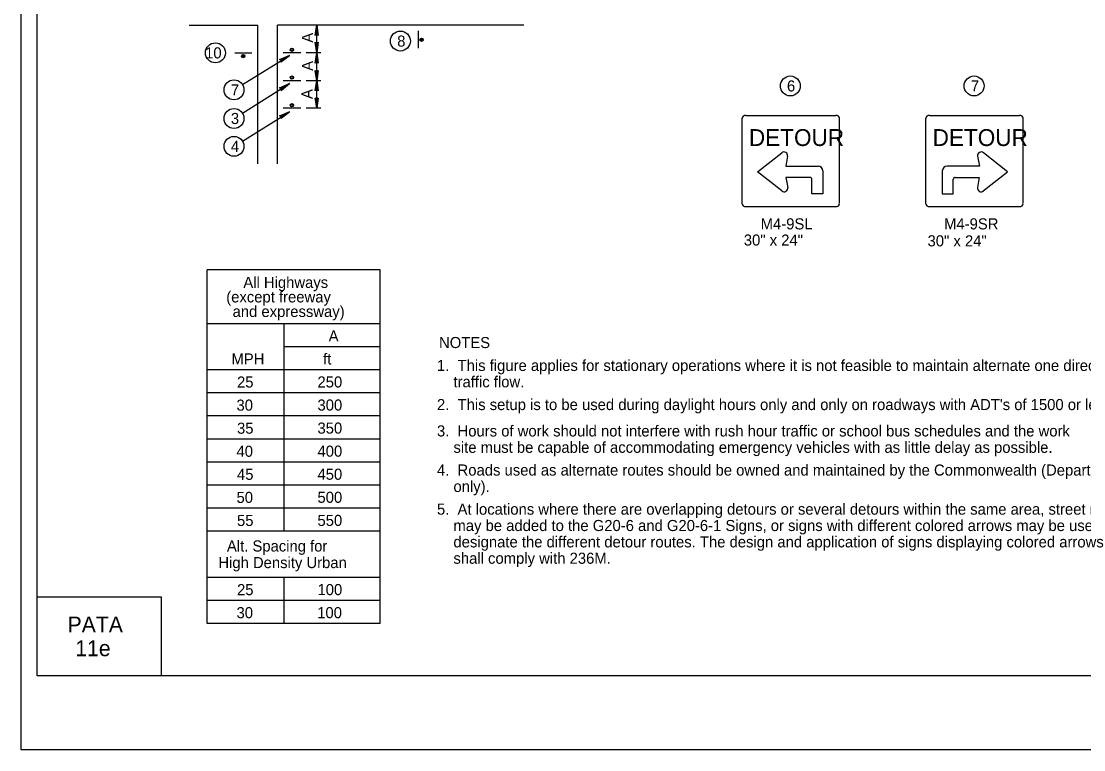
# Model space of a CAD drawing. Extents: x -14145 to -13662, y 30244 to 30661.
# Drawn here: x -13790.17 to -13770.05, y 30451.81 to 30465.61 of the extents above; entities that cross this region are included whole.
import ezdxf

# ---------------------------------------------------------------- set-up
doc = ezdxf.new("R2010")
doc.units = 0
for name, color, linetype in [('1', 7, 'Continuous'), ('10', 7, 'Continuous'), ('2', 7, 'Continuous'), ('3', 7, 'Continuous'), ('4', 7, 'Continuous'), ('61', 7, 'Continuous')]:
    doc.layers.add(name, color=color, linetype=linetype)

msp = doc.modelspace()

# ---------------------------------------------------------------- linework, layer by layer
at = {"layer": '1'}
for p, q in [((-13786.996, 30465.537), (-13785.691, 30465.537)), ((-13785.691, 30462.907), (-13785.691, 30465.537)), ((-13785.319, 30462.907), (-13785.319, 30465.537)), ((-13780.654, 30465.537), (-13785.319, 30465.537)), ((-13784.575, 30465.01), (-13784.575, 30465.544)), ((-13782.649, 30465.098), (-13782.649, 30465.429)), ((-13786.13, 30465.01), (-13785.806, 30465.01)), ((-13785.982, 30464.415), (-13785.096, 30464.963)), ((-13784.88, 30465.01), (-13785.211, 30465.01)), ((-13784.501, 30465.01), (-13784.778, 30465.01)), ((-13784.575, 30464.483), (-13784.575, 30465.01)), ((-13785.982, 30463.867), (-13785.096, 30464.429)), ((-13784.88, 30464.483), (-13785.211, 30464.483)), ((-13784.501, 30464.483), (-13784.778, 30464.483)), ((-13784.575, 30463.962), (-13784.575, 30464.489)), ((-13784.88, 30463.962), (-13785.211, 30463.962)), ((-13784.501, 30463.962), (-13784.778, 30463.962)), ((-13785.982, 30463.34), (-13785.096, 30463.894)), ((-13776.52, 30462.152), (-13776.52, 30463.774)), ((-13776.45, 30463.827), (-13774.748, 30463.827)), ((-13774.677, 30462.157), (-13774.677, 30463.774)), ((-13773.04, 30462.152), (-13773.04, 30463.774)), ((-13772.97, 30463.827), (-13771.268, 30463.827)), ((-13771.197, 30462.157), (-13771.197, 30463.774)), ((-13776.227, 30462.759), (-13775.77, 30463.12)), ((-13771.491, 30462.759), (-13771.948, 30463.12)), ((-13775.658, 30463.057), (-13775.692, 30462.866)), ((-13772.06, 30463.057), (-13772.026, 30462.866)), ((-13775.765, 30462.395), (-13776.227, 30462.759)), ((-13775.692, 30462.866), (-13775.082, 30462.866)), ((-13774.99, 30462.775), (-13774.99, 30462.343)), ((-13772.728, 30462.775), (-13772.728, 30462.343)), ((-13772.026, 30462.866), (-13772.636, 30462.866)), ((-13771.953, 30462.395), (-13771.491, 30462.759)), ((-13775.235, 30462.653), (-13775.689, 30462.653)), ((-13775.689, 30462.653), (-13775.654, 30462.46)), ((-13775.198, 30462.343), (-13775.198, 30462.616)), ((-13772.52, 30462.343), (-13772.52, 30462.616)), ((-13772.483, 30462.653), (-13772.029, 30462.653)), ((-13772.029, 30462.653), (-13772.064, 30462.46)), ((-13774.99, 30462.343), (-13775.198, 30462.343)), ((-13772.728, 30462.343), (-13772.52, 30462.343)), ((-13774.748, 30462.096), (-13776.45, 30462.096)), ((-13771.268, 30462.096), (-13772.97, 30462.096)), ((-13786.651, 30454.198), (-13786.651, 30460.898)), ((-13783.374, 30460.898), (-13786.651, 30460.898)), ((-13783.374, 30454.198), (-13783.374, 30460.898)), ((-13783.374, 30459.879), (-13786.653, 30459.879)), ((-13785.195, 30455.946), (-13785.195, 30459.879)), ((-13783.374, 30459.442), (-13785.195, 30459.442)), ((-13783.374, 30459.005), (-13786.653, 30459.005)), ((-13783.374, 30458.568), (-13786.653, 30458.568)), ((-13783.374, 30458.131), (-13786.653, 30458.131)), ((-13783.374, 30457.694), (-13786.653, 30457.694)), ((-13783.374, 30457.257), (-13786.653, 30457.257)), ((-13783.374, 30456.82), (-13786.653, 30456.82)), ((-13783.374, 30456.383), (-13786.653, 30456.383)), ((-13783.374, 30455.946), (-13786.653, 30455.946)), ((-13783.374, 30455.072), (-13786.653, 30455.072)), ((-13785.195, 30454.198), (-13785.195, 30455.072)), ((-13783.374, 30454.635), (-13786.653, 30454.635)), ((-13783.374, 30454.198), (-13786.651, 30454.198))]:
    msp.add_line(p, q, dxfattribs=at)
for points in [[(-13784.602, 30465.355), (-13784.589, 30465.362), (-13784.575, 30465.544), (-13784.602, 30465.355), (-13784.609, 30465.341), (-13784.575, 30465.544), (-13784.569, 30465.362), (-13784.555, 30465.355), (-13784.575, 30465.544), (-13784.548, 30465.341), (-13784.555, 30465.355)], [(-13784.555, 30465.199), (-13784.569, 30465.192), (-13784.575, 30465.01), (-13784.555, 30465.199), (-13784.548, 30465.213), (-13784.575, 30465.01), (-13784.589, 30465.192), (-13784.602, 30465.199), (-13784.575, 30465.01), (-13784.609, 30465.213), (-13784.602, 30465.199)], [(-13785.272, 30464.888), (-13785.258, 30464.882), (-13785.096, 30464.963), (-13785.272, 30464.888), (-13785.285, 30464.888), (-13785.096, 30464.963), (-13785.245, 30464.861), (-13785.245, 30464.848), (-13785.096, 30464.963), (-13785.251, 30464.834), (-13785.245, 30464.848)], [(-13784.602, 30464.821), (-13784.589, 30464.834), (-13784.575, 30465.01), (-13784.602, 30464.821), (-13784.609, 30464.814), (-13784.575, 30465.01), (-13784.569, 30464.834), (-13784.555, 30464.827), (-13784.575, 30465.01), (-13784.548, 30464.814), (-13784.555, 30464.827)], [(-13784.555, 30464.672), (-13784.569, 30464.665), (-13784.575, 30464.483), (-13784.555, 30464.672), (-13784.548, 30464.679), (-13784.575, 30464.483), (-13784.589, 30464.665), (-13784.602, 30464.672), (-13784.575, 30464.483), (-13784.609, 30464.679), (-13784.602, 30464.672)], [(-13785.272, 30464.341), (-13785.258, 30464.334), (-13785.096, 30464.429), (-13785.272, 30464.341), (-13785.285, 30464.347), (-13785.096, 30464.429), (-13785.245, 30464.32), (-13785.245, 30464.307), (-13785.096, 30464.429), (-13785.251, 30464.293), (-13785.245, 30464.307)], [(-13784.602, 30464.307), (-13784.589, 30464.314), (-13784.575, 30464.489), (-13784.602, 30464.307), (-13784.609, 30464.293), (-13784.575, 30464.489), (-13784.569, 30464.314), (-13784.555, 30464.307), (-13784.575, 30464.489), (-13784.548, 30464.293), (-13784.555, 30464.307)], [(-13784.555, 30464.151), (-13784.569, 30464.145), (-13784.575, 30463.962), (-13784.555, 30464.151), (-13784.548, 30464.151), (-13784.575, 30463.962), (-13784.589, 30464.145), (-13784.602, 30464.151), (-13784.575, 30463.962), (-13784.609, 30464.151), (-13784.602, 30464.151)], [(-13785.272, 30463.82), (-13785.258, 30463.813), (-13785.096, 30463.894), (-13785.272, 30463.82), (-13785.285, 30463.82), (-13785.096, 30463.894), (-13785.245, 30463.793), (-13785.245, 30463.78), (-13785.096, 30463.894), (-13785.251, 30463.766), (-13785.245, 30463.78)]]:
    msp.add_lwpolyline(points, dxfattribs=at)
for centre, radius in [((-13782.993, 30465.236), 0.189), ((-13786.496, 30465.012), 0.189), ((-13782.59, 30465.259), 0.0314), ((-13785.968, 30464.951), 0.0314), ((-13785.048, 30465.072), 0.0314), ((-13785.048, 30464.544), 0.0314), ((-13775.607, 30464.385), 0.189), ((-13772.127, 30464.385), 0.189), ((-13786.144, 30464.311), 0.189), ((-13786.144, 30463.768), 0.189), ((-13785.048, 30464.02), 0.0314), ((-13786.144, 30463.241), 0.189)]:
    msp.add_circle(centre, radius, dxfattribs=at)
for centre, radius, start, end in [((-13782.589, 30465.259), 0.0174, 175.7499, 170.479), ((-13785.967, 30464.95), 0.0174, 85.7499, 80.479), ((-13785.049, 30465.073), 0.0174, 265.7499, 260.479), ((-13785.049, 30464.545), 0.0174, 265.7499, 260.479), ((-13785.049, 30464.021), 0.0174, 265.7499, 260.479), ((-13775.726, 30463.066), 0.0682, 349.4753, 130.1409), ((-13771.992, 30463.066), 0.0682, 49.8591, 190.5247), ((-13775.081, 30462.774), 0.0913, 0, 90), ((-13772.637, 30462.774), 0.0913, 90, 180), ((-13775.235, 30462.616), 0.0365, 0, 90), ((-13772.483, 30462.616), 0.0365, 90, 180), ((-13775.723, 30462.448), 0.0682, 227.8458, 11.7524), ((-13771.995, 30462.448), 0.0682, 168.2476, 312.1543)]:
    msp.add_arc(centre, radius, start, end, dxfattribs=at)
for centre, major_axis, start_param, end_param in [((-13776.45, 30463.774), (-0.0703, 0), 4.712389, 6.283185), ((-13774.747, 30463.774), (-0.0703, 0), 3.141593, 4.712389), ((-13772.97, 30463.774), (-0.0703, 0), 4.712389, 6.283185), ((-13771.267, 30463.774), (-0.0703, 0), 3.141593, 4.712389), ((-13776.45, 30462.152), (0.0703, 0), 3.141593, 4.712389), ((-13774.747, 30462.152), (0.0703, 0), 4.712389, 6.283185), ((-13772.97, 30462.152), (0.0703, 0), 3.141593, 4.712389), ((-13771.267, 30462.152), (0.0703, 0), 4.712389, 6.283185)]:
    msp.add_ellipse(centre, major_axis=major_axis, ratio=0.769231, start_param=start_param, end_param=end_param, dxfattribs=at)
at = {"layer": '10'}
for p, q in [((-13789.874, 30453.207), (-13789.874, 30475.777)), ((-13789.874, 30454.707), (-13787.524, 30454.707)), ((-13787.524, 30454.707), (-13787.524, 30453.207)), ((-13758.422, 30453.207), (-13789.874, 30453.207))]:
    msp.add_line(p, q, dxfattribs=at)
at = {"layer": '61'}
msp.add_lwpolyline([(-13790.174, 30477.307), (-13757.174, 30477.307), (-13757.174, 30451.807), (-13790.174, 30451.807)], close=True, dxfattribs=at)

# ---------------------------------------------------------------- texts
at = {"layer": '1'}
for p in [(-13784.649, 30465.205), (-13784.649, 30464.671), (-13784.656, 30464.137)]:
    msp.add_text('A', height=0.21, rotation=90, dxfattribs=at).set_placement(p)
for s, height, p in [('8', 0.21, (-13783.053, 30465.13)), ('10', 0.21, (-13786.691, 30464.907)), ('7', 0.21, (-13786.203, 30464.204)), ('6', 0.21, (-13775.671, 30464.28)), ('7', 0.21, (-13772.187, 30464.28)), ('3', 0.21, (-13786.203, 30463.663)), ('DETOUR', 0.3195, (-13776.392, 30463.247)), ('DETOUR', 0.3195, (-13772.912, 30463.247)), ('4', 0.21, (-13786.203, 30463.136))]:
    msp.add_text(s, height=height, dxfattribs=at).set_placement(p)
at = {"layer": '2'}
for s, p in [('M4-9SL', (-13776.169, 30461.667)), ('M4-9SR', (-13772.695, 30461.667)), ('30" x 24"', (-13776.488, 30461.36)), ('30" x 24"', (-13773.008, 30461.345)), ('A', (-13784.351, 30459.544)), ('NOTES', (-13782.261, 30459.418)), ('MPH', (-13786.192, 30459.107)), ('ft', (-13784.456, 30459.107)), ('1.  This figure applies for stationary operations where it is not feasible to maintain alternate one direction ', (-13782.3, 30458.984)), ('25', (-13786.087, 30458.67)), ('250', (-13784.563, 30458.671)), ('    traffic flow.', (-13782.3, 30458.674)), ('30', (-13786.097, 30458.232)), ('300', (-13784.563, 30458.234)), ("2.  This setup is to be used during daylight hours only and only on roadways with ADT's of 1500 or less.", (-13782.3, 30458.243)), ('35', (-13786.087, 30457.795)), ('350', (-13784.563, 30457.797)), ('3.  Hours of work should not interfere with rush hour traffic or school bus schedules and the work ', (-13782.3, 30457.743)), ('40', (-13786.097, 30457.358)), ('400', (-13784.563, 30457.36)), ('    site must be capable of accommodating emergency vehicles with as little delay as possible.', (-13782.3, 30457.433)), ('45', (-13786.087, 30456.921)), ('450', (-13784.563, 30456.923)), ('4.  Roads used as alternate routes should be owned and maintained by the Commonwealth (Department projects ', (-13782.3, 30457.002)), ('    only).', (-13782.3, 30456.692)), ('50', (-13786.096, 30456.484)), ('500', (-13784.563, 30456.486)), ('5.  At locations where there are overlapping detours or several detours within the same area, street names ', (-13782.3, 30456.261)), ('550', (-13784.563, 30456.048)), ('55', (-13786.087, 30456.047)), ('    may be added to the G20-6 and G20-6-1 Signs, or signs with different colored arrows may be used to ', (-13782.3, 30455.951)), ('    designate the different detour routes. The design and application of signs displaying colored arrows ', (-13782.3, 30455.641)), ('    shall comply with 236M.', (-13782.3, 30455.331)), ('25', (-13786.087, 30454.736)), ('100', (-13784.563, 30454.737)), ('100', (-13784.563, 30454.737)), ('100', (-13784.563, 30454.737)), ('100', (-13784.563, 30454.737)), ('30', (-13786.096, 30454.299)), ('100', (-13784.568, 30454.3)), ('100', (-13784.568, 30454.3)), ('100', (-13784.568, 30454.3)), ('100', (-13784.568, 30454.3))]:
    msp.add_text(s, height=0.21, dxfattribs=at).set_placement(p)
at = {"layer": '3'}
for s, height, p in [('All Highways', 0.20979, (-13785.967, 30460.558)), ('(except freeway ', 0.21, (-13786.291, 30460.283)), ('and expressway)', 0.21, (-13786.171, 30460.007)), ('Alt. Spacing for', 0.20979, (-13786.278, 30455.563)), ('High Density Urban', 0.20979, (-13786.44, 30455.249))]:
    msp.add_text(s, height=height, dxfattribs=at).set_placement(p)
at = {"layer": '4'}
for s, p in [('PATA', (-13789.296, 30454.03)), ('11e', (-13789.15, 30453.58))]:
    msp.add_text(s, height=0.3, dxfattribs=at).set_placement(p)

doc.saveas('drawing.dxf')
